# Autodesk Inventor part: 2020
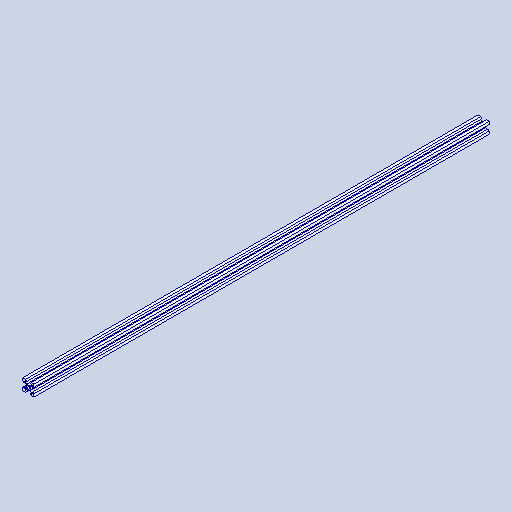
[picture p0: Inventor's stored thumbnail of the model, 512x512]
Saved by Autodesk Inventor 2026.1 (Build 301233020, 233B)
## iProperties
Created: 2024-09
Part Number: 2020
Material: Alluminio 6061
Document SubType Name: Modeling
Designer: hp
Density: 2.7 g/cm^3
Appearance: Default
Author: hp
Revision Number: ANY
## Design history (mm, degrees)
node "Solido1"
sketch "Sketch3"
  geometry: 2 further points
hole "Hole3" sketch "Sketch3" at (32.222, -3.027), (16.972, -3.027) diameter "d14" = 4.5; stored, may be unused: countersink angle "d18" = 90 deg, drill point angle "d20" = 0 deg; dims "d15" = 6, "d16" = 4, "d17" = 2, "d19" = 8
sketch "Sketch6"
  geometry: 2 further points
hole "Hole6" sketch "Sketch6" at (797, 3.053), (810, 3.053) diameter "d35" = 4.5; stored, may be unused: countersink angle "d39" = 90 deg, drill point angle "d41" = 0 deg; dims "d36" = 6, "d37" = 4, "d38" = 2, "d40" = 8
sketch "Sketch7"
  geometry: 2 further points
hole "Hole7" sketch "Sketch7" at (93.5, -3.027), (109.5, -3.027) diameter "d42" = 3.4; stored, may be unused: countersink angle "d46" = 90 deg, drill point angle "d48" = 0 deg; dims "d43" = 6, "d44" = 4, "d45" = 2, "d47" = 8
sketch "Sketch8"
  geometry: 4 further points
hole "Hole8" sketch "Sketch8" at (748, 3.003), (764, 3.003), (64, 3.003), (80, 3.003) diameter "d49" = 4.5; stored, may be unused: countersink angle "d53" = 90 deg, drill point angle "d55" = 0 deg; dims "d50" = 6, "d51" = 4, "d52" = 2, "d54" = 8
sketch "Sketch9"
  geometry: 2 further points
hole "Hole9" sketch "Sketch9" at (692.5, -3.027), (708.5, -3.027) diameter "d56" = 3.4; stored, may be unused: countersink angle "d60" = 90 deg, drill point angle "d62" = 0 deg; dims "d57" = 6, "d58" = 4, "d59" = 2, "d61" = 8
body "Solid1"
